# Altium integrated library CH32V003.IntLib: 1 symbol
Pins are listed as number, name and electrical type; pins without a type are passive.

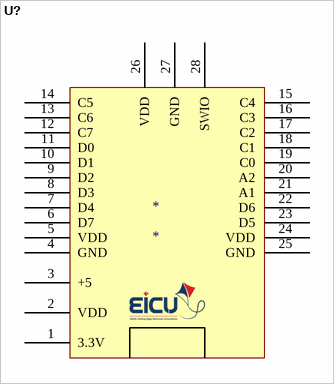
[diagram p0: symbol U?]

## U?
designator *
EICUT.com
footprint PCBComponent_1
pins: 1 3.3V, 2 VDD, 3 +5, 4 GND, 5 VDD, 6 D7, 7 D4, 8 D3, 9 D2, 10 D1, 11 D0, 12 C7, 13 C6, 14 C5, 15 C4, 16 C3, 17 C2, 18 C1, 19 C0, 20 A2, 21 A1, 22 D6, 23 D5, 24 VDD, 25 GND, 26 VDD, 27 GND, 28 SWIO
